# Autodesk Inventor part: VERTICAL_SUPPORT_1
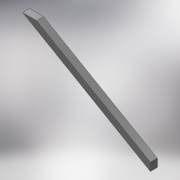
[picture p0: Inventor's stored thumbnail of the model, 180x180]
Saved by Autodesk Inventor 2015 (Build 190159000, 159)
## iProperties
Created: 2014-08
Part Number: VERTICAL_SUPPORT_1
Material: Steel, Mild
Document SubType Name: Modeling
Designer: lakshayg
Density: 7.85 g/cm^3
Appearance: Semi-Polished
Mass: 271.458 g
Surface Area: 119.812 cm^2
Volume: 34.5807 cm^3
Author: lakshayg
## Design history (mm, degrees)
sketch "Sketch1"
  geometry: L1 (0, 0)-(195.97, 0); L2 (0, 0)-(0, -113.144); L3 (0, -113.144)-(195.97, 0); L4 (219.97, 0)-(0, -127); L5 (219.97, 0)-(195.97, 0); L6 (0, -113.144)-(0, -127)
  constraints: 12 end point, 2 collinear, 2 point on line, 1 horizontal, 1 parallel, 1 vertical
  dimensions: "d2" = 12 distance between parallel lines of L4 L3; "d5" = 254 distance of L4.start L4.end; "d6" = 30 deg angle of L1 L3
extrude "Extrusion1" new body sketch "Sketch1" distance "d3" = 12; taper "d4" = 0 deg
body "Solid1"
